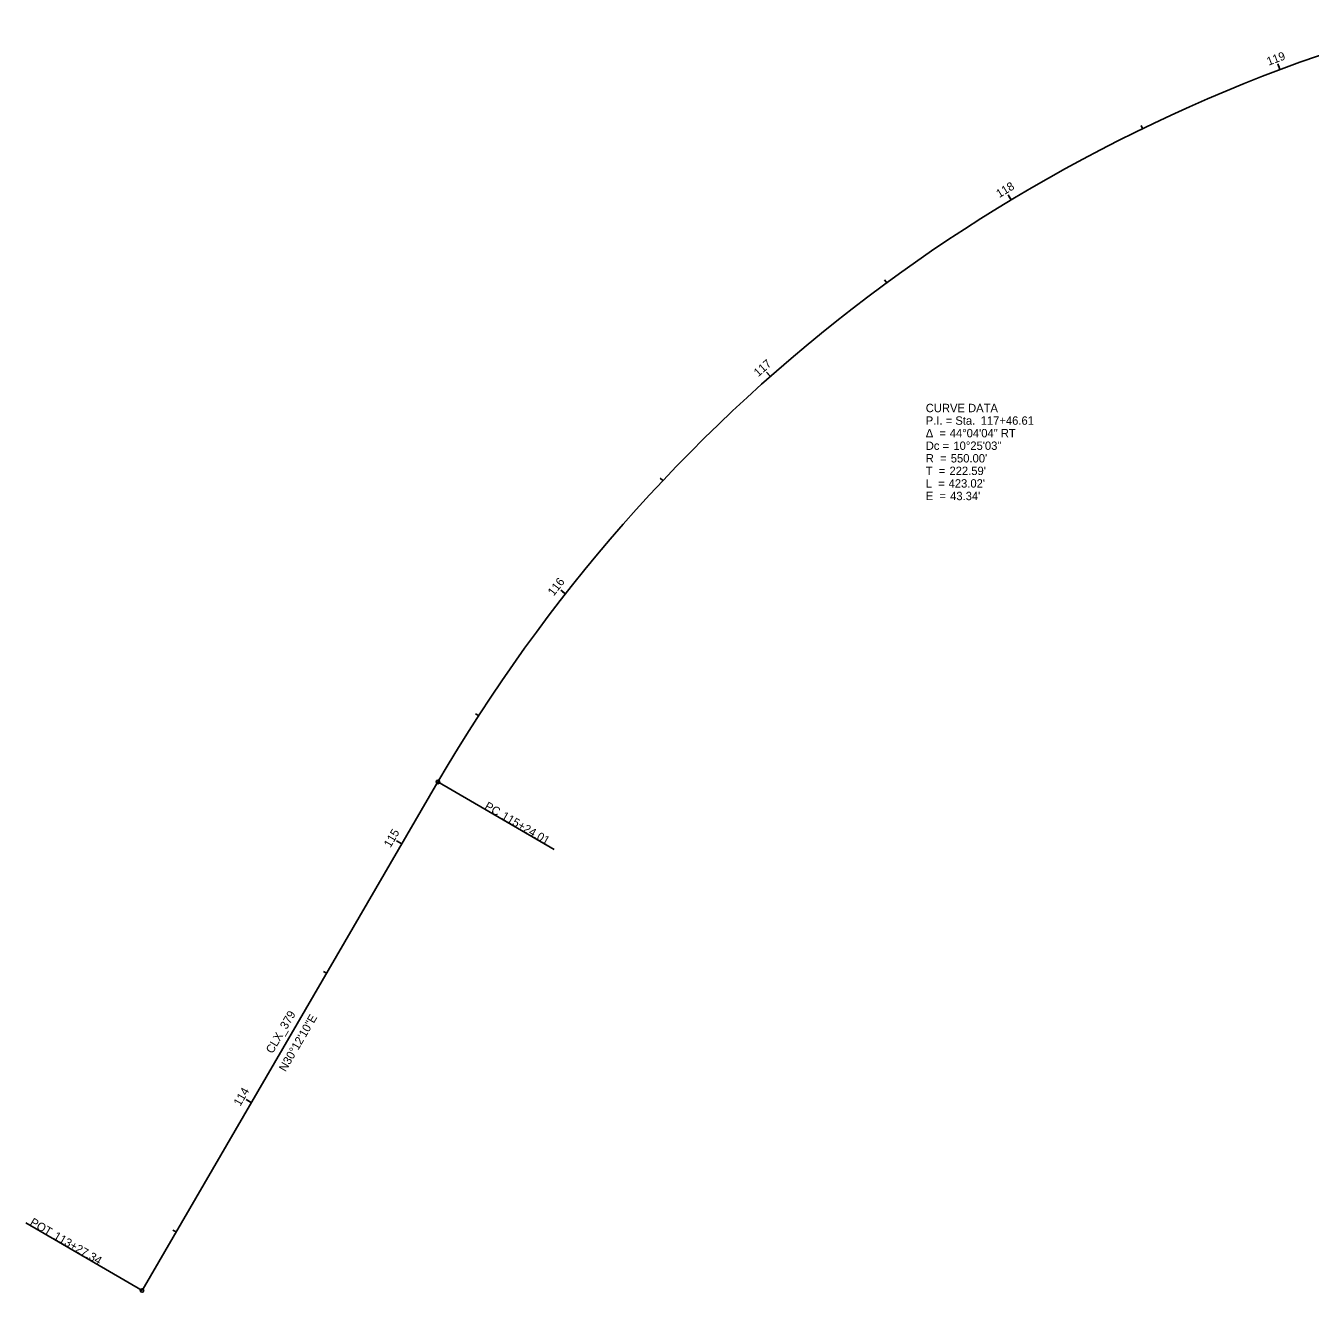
# Model space of a CAD drawing. Extents: x 2325404 to 2326256, y 693508 to 694271.
# Drawn here: x 2325404.1 to 2325833.6, y 693507.6 to 693930.9 of the extents above; entities that cross this region are included whole.
import ezdxf

# ---------------------------------------------------------------- set-up
doc = ezdxf.new("R2010")
doc.units = 0
for name, color, linetype in [('GE_X_Alignment', 7, 'Continuous'), ('GE_X_Alignment_1000_Curve_Data', 7, 'Continuous'), ('GE_X_Alignment_1000_Stations', 7, 'Continuous'), ('GE_X_Alignment_100_Curve_Data', 7, 'Continuous'), ('GE_X_Alignment_100_Stations', 7, 'Continuous'), ('GE_X_Alignment_500_Curve_Data', 7, 'Continuous'), ('GE_X_Alignment_500_Stations', 7, 'Continuous')]:
    doc.layers.add(name, color=color, linetype=linetype)

msp = doc.modelspace()

# ---------------------------------------------------------------- linework, layer by layer
at = {"layer": 'GE_X_Alignment'}
msp.add_line((2325443, 693508.19), (2325541.94, 693678.16), dxfattribs=at)
msp.add_arc((2326017.28, 693401.48), 550, 105.7296, 149.7973, dxfattribs=at)
at = {"layer": 'GE_X_Alignment_1000_Stations'}
for p, q in [((2325541.94, 693678.16), (2325580.83, 693655.53)), ((2325529.86, 693657.41), (2325528.82, 693658.01)), ((2325443, 693508.19), (2325404.11, 693530.83))]:
    msp.add_line(p, q, dxfattribs=at)
for centre in [(2325541.94, 693678.16), (2325443, 693508.19)]:
    msp.add_circle(centre, 0.6, dxfattribs=at)
at = {"layer": 'GE_X_Alignment_100_Stations'}
for p, q in [((2325823.5, 693916.22), (2325822.8, 693918.09)), ((2325777.57, 693896.5), (2325777.05, 693897.58)), ((2325733.62, 693872.69), (2325732.59, 693874.41)), ((2325692.02, 693845), (2325691.31, 693845.96)), ((2325653.1, 693813.64), (2325651.77, 693815.13)), ((2325617.18, 693778.87), (2325616.31, 693779.69)), ((2325584.57, 693740.99), (2325583, 693742.23)), ((2325555.54, 693700.31), (2325554.53, 693700.96)), ((2325541.94, 693678.16), (2325580.83, 693655.53)), ((2325529.86, 693657.41), (2325528.13, 693658.42)), ((2325504.71, 693614.2), (2325503.67, 693614.8)), ((2325479.55, 693570.99), (2325477.82, 693571.99)), ((2325443, 693508.19), (2325404.11, 693530.83)), ((2325454.4, 693527.77), (2325453.36, 693528.38))]:
    msp.add_line(p, q, dxfattribs=at)
for centre in [(2325541.94, 693678.16), (2325443, 693508.19)]:
    msp.add_circle(centre, 0.6, dxfattribs=at)
at = {"layer": 'GE_X_Alignment_500_Stations'}
for p, q in [((2325823.5, 693916.22), (2325823.08, 693917.34)), ((2325733.62, 693872.69), (2325733, 693873.72)), ((2325653.1, 693813.64), (2325652.3, 693814.53)), ((2325584.57, 693740.99), (2325583.63, 693741.73)), ((2325541.94, 693678.16), (2325580.83, 693655.53)), ((2325529.86, 693657.41), (2325528.13, 693658.42)), ((2325479.55, 693570.99), (2325478.52, 693571.59)), ((2325443, 693508.19), (2325404.11, 693530.83))]:
    msp.add_line(p, q, dxfattribs=at)
for centre in [(2325541.94, 693678.16), (2325443, 693508.19)]:
    msp.add_circle(centre, 0.6, dxfattribs=at)

# ---------------------------------------------------------------- texts
at = {"layer": 'GE_X_Alignment_1000_Curve_Data'}
for s, p in [('CURVE DATA', (2325705.06, 693801.72)), ('P.I. = Sta. ', (2325705.06, 693797.52)), ('117+46.61', (2325723.43, 693797.52)), ('Δ  = ', (2325705.06, 693793.32)), ('44°04\'04" RT', (2325713.08, 693793.32)), ('Dc = ', (2325705.06, 693789.12)), ('10°25\'03"', (2325714.3, 693789.12)), ('R  = ', (2325705.06, 693784.92)), ("550.00'", (2325713.42, 693784.92)), ('T  = ', (2325705.06, 693780.72)), ("222.59'", (2325712.99, 693780.72)), ('L  = ', (2325705.06, 693776.52)), ("423.02'", (2325712.7, 693776.52)), ('E  = ', (2325705.06, 693772.32)), ("43.34'", (2325713.21, 693772.32))]:
    msp.add_text(s, height=2.8, dxfattribs=at).set_placement(p)
at = {"layer": 'GE_X_Alignment_1000_Stations'}
for s, rotation, p in [('PC', 329.7973, (2325557.29, 693669.28)), ('115+24.01', 329.7973, (2325562.93, 693666)), ('CLX_379', 59.7973, (2325486.64, 693587.14)), ('N30°12\'10"E', 59.7973, (2325490.99, 693581.1)), ('POT', 329.7973, (2325405.26, 693530.21)), ('113+27.34', 329.7973, (2325413.15, 693525.62))]:
    msp.add_text(s, height=2.8, rotation=rotation, dxfattribs=at).set_placement(p)
at = {"layer": 'GE_X_Alignment_100_Curve_Data'}
for s, p in [('CURVE DATA', (2325705.06, 693801.72)), ('P.I. = Sta. ', (2325705.06, 693797.52)), ('117+46.61', (2325723.43, 693797.52)), ('Δ  = ', (2325705.06, 693793.32)), ('44°04\'04" RT', (2325713.08, 693793.32)), ('Dc = ', (2325705.06, 693789.12)), ('10°25\'03"', (2325714.3, 693789.12)), ('R  = ', (2325705.06, 693784.92)), ("550.00'", (2325713.42, 693784.92)), ('T  = ', (2325705.06, 693780.72)), ("222.59'", (2325712.99, 693780.72)), ('L  = ', (2325705.06, 693776.52)), ("423.02'", (2325712.7, 693776.52)), ('E  = ', (2325705.06, 693772.32)), ("43.34'", (2325713.21, 693772.32))]:
    msp.add_text(s, height=2.8, dxfattribs=at).set_placement(p)
at = {"layer": 'GE_X_Alignment_100_Stations'}
for s, rotation, p in [('119', 20.6293, (2325819.7, 693917.5)), ('118', 31.0467, (2325729.63, 693873.26)), ('117', 41.4641, (2325649.05, 693813.39)), ('116', 51.8815, (2325580.63, 693740.09)), ('PC', 329.7973, (2325557.29, 693669.28)), ('115+24.01', 329.7973, (2325562.93, 693666)), ('115', 59.7973, (2325526.07, 693655.97)), ('CLX_379', 59.7973, (2325486.64, 693587.14)), ('N30°12\'10"E', 59.7973, (2325490.99, 693581.1)), ('114', 59.7973, (2325475.84, 693569.57)), ('POT', 329.7973, (2325405.26, 693530.21)), ('113+27.34', 329.7973, (2325413.15, 693525.62))]:
    msp.add_text(s, height=2.8, rotation=rotation, dxfattribs=at).set_placement(p)
at = {"layer": 'GE_X_Alignment_500_Curve_Data'}
for s, p in [('CURVE DATA', (2325705.06, 693801.72)), ('P.I. = Sta. ', (2325705.06, 693797.52)), ('117+46.61', (2325723.43, 693797.52)), ('Δ  = ', (2325705.06, 693793.32)), ('44°04\'04" RT', (2325713.08, 693793.32)), ('Dc = ', (2325705.06, 693789.12)), ('10°25\'03"', (2325714.3, 693789.12)), ('R  = ', (2325705.06, 693784.92)), ("550.00'", (2325713.42, 693784.92)), ('T  = ', (2325705.06, 693780.72)), ("222.59'", (2325712.99, 693780.72)), ('L  = ', (2325705.06, 693776.52)), ("423.02'", (2325712.7, 693776.52)), ('E  = ', (2325705.06, 693772.32)), ("43.34'", (2325713.21, 693772.32))]:
    msp.add_text(s, height=2.8, dxfattribs=at).set_placement(p)
at = {"layer": 'GE_X_Alignment_500_Stations'}
for s, rotation, p in [('PC', 329.7973, (2325557.29, 693669.28)), ('115+24.01', 329.7973, (2325562.93, 693666)), ('115', 59.7973, (2325526.07, 693655.97)), ('CLX_379', 59.7973, (2325486.64, 693587.14)), ('N30°12\'10"E', 59.7973, (2325490.99, 693581.1)), ('POT', 329.7973, (2325405.26, 693530.21)), ('113+27.34', 329.7973, (2325413.15, 693525.62))]:
    msp.add_text(s, height=2.8, rotation=rotation, dxfattribs=at).set_placement(p)

doc.saveas('drawing.dxf')
